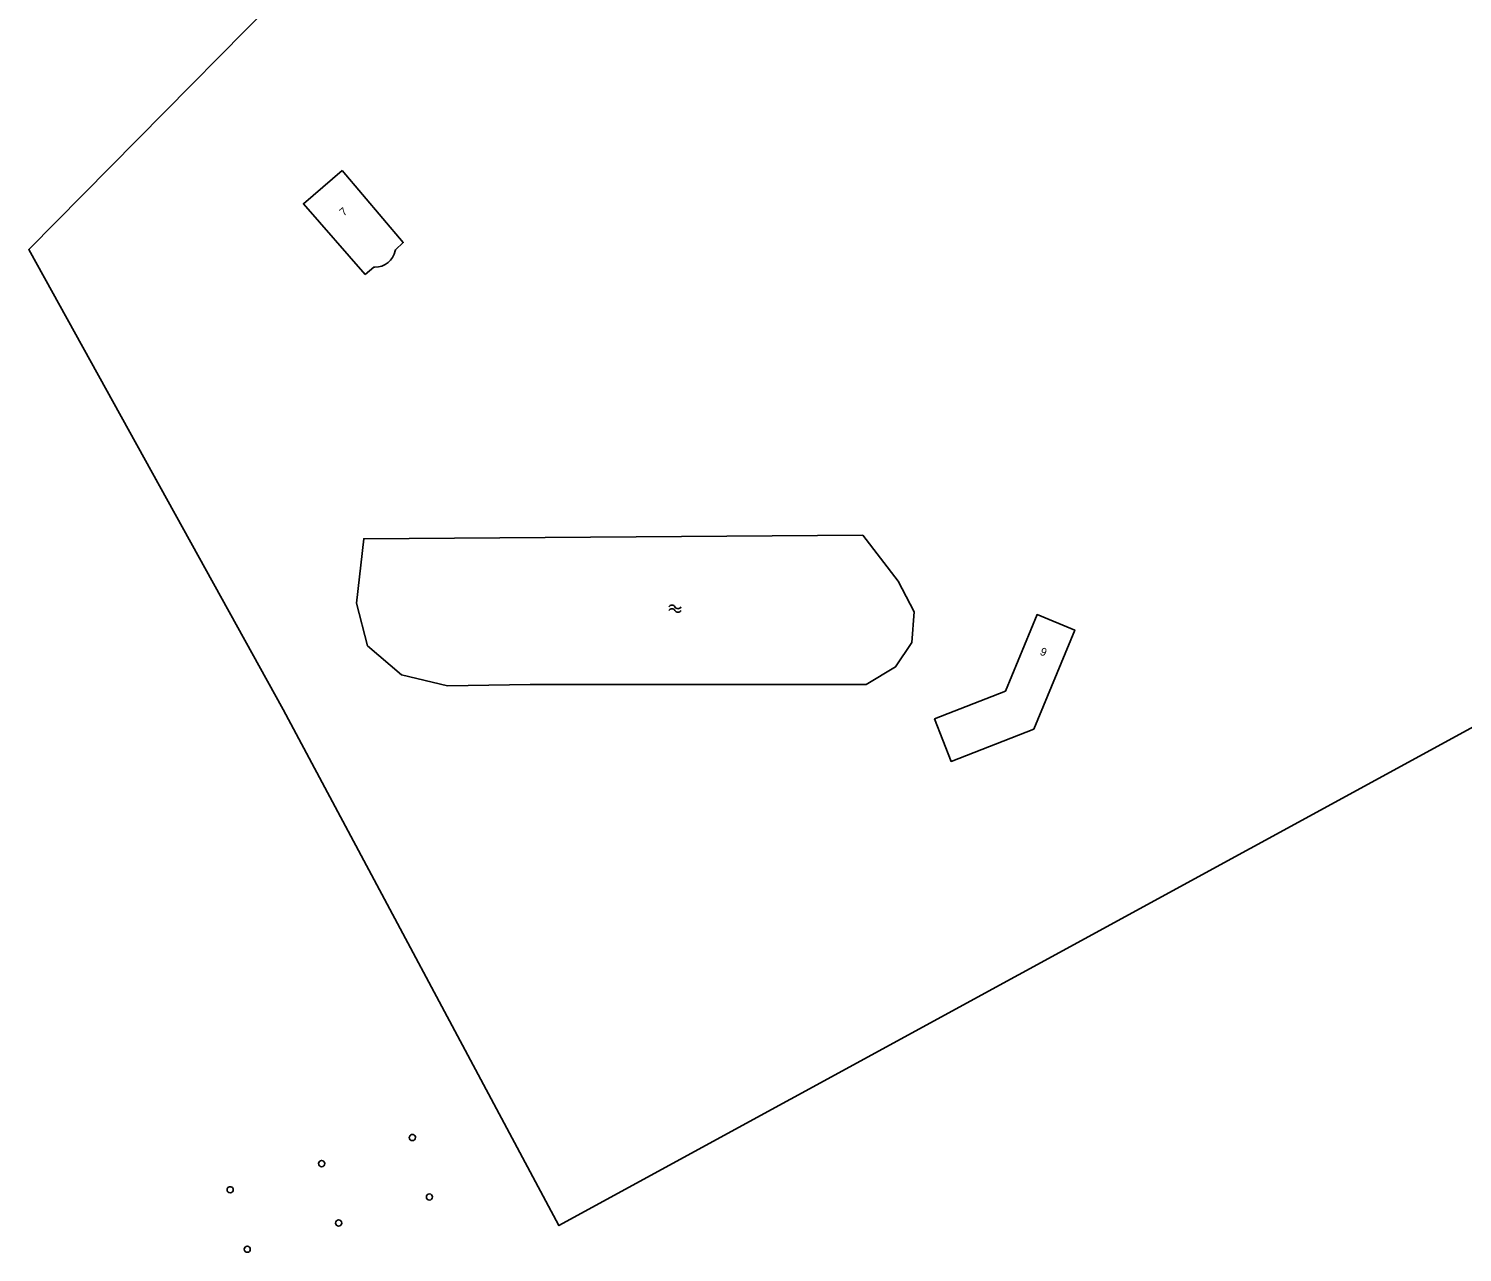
# Model space of a CAD drawing. Extents: x 135990 to 139000, y 393500 to 396000.
# Drawn here: x 137429.3 to 137608.5, y 395550.1 to 395703 of the extents above; entities that cross this region are included whole.
import ezdxf

# ---------------------------------------------------------------- set-up
doc = ezdxf.new("R2010")
doc.units = 0
for name, color, linetype in [('gg-anno-huisnummerreeks BGT', 7, 'Continuous'), ('gg-bbg-gedigitaliseerde bebouwing', 7, 'Continuous'), ('gg-bbg-hoofdgebouw', 7, 'Continuous'), ('gg-bbg-hoogspanningsmast', 7, 'Continuous'), ('gg-kntw-bovenkant insteek waterloop', 7, 'Continuous'), ('gt-symb-watersymbool', 7, 'Continuous'), ('gx-grn-maaiveld', 7, 'Continuous')]:
    doc.layers.add(name, color=color, linetype=linetype)

# ---------------------------------------------------------------- blocks, each defined once
blk = doc.blocks.new('gt0-WA')
at = {"layer": 'gt-symb-watersymbool'}
for centre, start, end in [((-0.32, 0.02), 28.0725, 151.9275), ((0.43, 0.42), 208.0725, 331.9275), ((-0.32, -0.43), 28.0725, 151.9275), ((0.43, -0.03), 208.0725, 331.9275)]:
    blk.add_arc(centre, 0.425, start, end, dxfattribs=at)

msp = doc.modelspace()

# ---------------------------------------------------------------- linework, layer by layer
at = {"layer": 'gg-bbg-gedigitaliseerde bebouwing'}
for points in [[(137471.37, 395672.322), (137463.638, 395681.158), (137468.48, 395685.3)], [(137551.363, 395620.252), (137555.312, 395629.828), (137560.015, 395627.888), (137554.915, 395615.524)], [(137551.363, 395620.252), (137542.497, 395616.778), (137544.576, 395611.473), (137554.915, 395615.524)]]:
    msp.add_lwpolyline(points, dxfattribs=at)
at = {"layer": 'gg-bbg-hoofdgebouw'}
for points in [[(137468.48, 395685.3), (137476.11, 395676.311), (137475.14, 395675.422), (137475.11, 395675.291)], [(137472.561, 395673.241), (137472.42, 395673.242), (137471.37, 395672.322)]]:
    msp.add_lwpolyline(points, dxfattribs=at)
msp.add_arc((137472.615, 395675.784), 2.543, 268.78505, 348.83, dxfattribs=at)
at = {"layer": 'gg-bbg-hoogspanningsmast'}
for centre, start, end in [((137477.257, 395564.477), 0.07431, 180.22217), ((137477.257, 395564.477), 180.22217, 0.07431), ((137465.906, 395561.224), 360, 180), ((137465.906, 395561.224), 180, 0), ((137454.484, 395557.948), 0.14805, 180.14805), ((137454.484, 395557.948), 180.14805, 0.14805), ((137479.387, 395557.05), 360, 180), ((137479.387, 395557.05), 180, 0), ((137468.035, 395553.795), 0.22236, 180.22236), ((137468.035, 395553.795), 180.22236, 0.22236), ((137456.613, 395550.521), 0, 180), ((137456.613, 395550.521), 180, 0)]:
    msp.add_arc(centre, 0.387, start, end, dxfattribs=at)
at = {"layer": 'gg-kntw-bovenkant insteek waterloop'}
for points in [[(137533.554, 395639.752), (137471.174, 395639.296), (137470.263, 395631.248), (137471.629, 395625.933), (137475.879, 395622.289), (137481.646, 395620.922), (137491.967, 395621.074)], [(137491.967, 395621.074), (137533.937, 395621.074), (137537.628, 395623.279), (137539.679, 395626.355), (137539.953, 395630.184), (137537.97, 395634.012), (137533.554, 395639.752)]]:
    msp.add_lwpolyline(points, dxfattribs=at)
at = {"layer": 'gx-grn-maaiveld'}
msp.add_lwpolyline([(137672.006, 395644.681), (137668.309, 395647.698), (137495.557, 395553.472), (137461.091, 395617.952), (137429.305, 395675.435), (137473.439, 395720.143), (137512.81, 395760.026)], dxfattribs=at)

# ---------------------------------------------------------------- block references
at = {"layer": 'gt-symb-watersymbool'}
msp.add_blockref('gt0-WA', (137510.01, 395630.56), dxfattribs=at)

# ---------------------------------------------------------------- texts
at = {"layer": 'gg-anno-huisnummerreeks BGT'}
for s, rotation, p in [('7', 40.5, (137468.675, 395679.546)), ('9', 337.6, (137555.589, 395624.846))]:
    msp.add_text(s, height=1, rotation=rotation, dxfattribs=at).set_placement(p)

doc.saveas('drawing.dxf')
